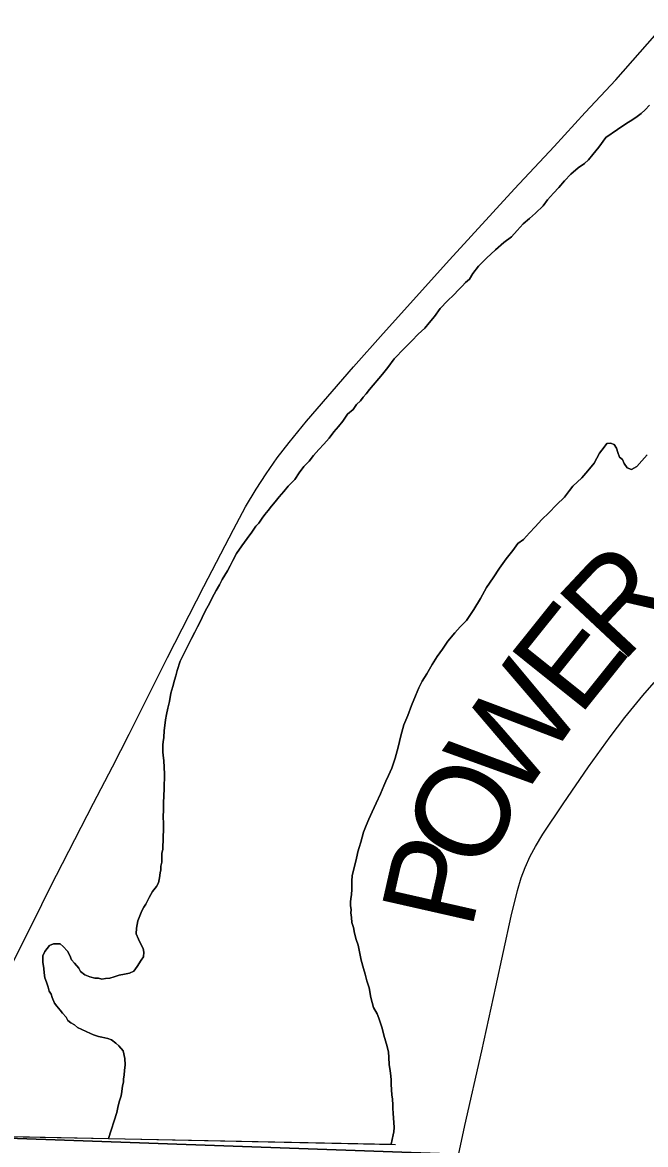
# Model space of a CAD drawing. Extents: x 2.4 to 73.1, y 4.5 to 25.6.
# Drawn here: x 33.9507 to 34.1404, y 20.0736 to 20.4152 of the extents above; entities that cross this region are included whole.
import ezdxf

# ---------------------------------------------------------------- set-up
doc = ezdxf.new("R2010")
doc.units = 0
for name, color, linetype in [('GM_X_County_Road', 7, 'Continuous'), ('GM_X_County_Road_Text', 7, 'Continuous'), ('GM_X_Major_River', 7, 'Continuous'), ('GM_X_Minor_River', 7, 'Continuous'), ('GM_X_State_Route', 7, 'Continuous'), ('SH_Cut_Line', 7, 'Continuous')]:
    doc.layers.add(name, color=color, linetype=linetype)

msp = doc.modelspace()

# ---------------------------------------------------------------- linework, layer by layer
at = {"layer": 'GM_X_County_Road'}
msp.add_lwpolyline([(34.08344, 20.07038), (34.08542, 20.07939), (34.09056, 20.10213), (34.09483, 20.12156), (34.0995, 20.14313), (34.10142, 20.15095), (34.10256, 20.1548), (34.10374, 20.15797), (34.10525, 20.16134), (34.10684, 20.16434), (34.10908, 20.16804), (34.11526, 20.17735), (34.12304, 20.1886), (34.12957, 20.19767), (34.13405, 20.20361), (34.13957, 20.21032), (34.14303, 20.21429)], dxfattribs=at)
at = {"layer": 'GM_X_Major_River'}
for p, q in [((34.06432, 20.07347), (33.88268, 20.07732)), ((33.97691, 20.07544), (34.06299, 20.07369))]:
    msp.add_line(p, q, dxfattribs=at)
for points in [[(34.1416, 20.39007), (34.14022, 20.38859), (34.13904, 20.38749), (34.13787, 20.38658), (34.13651, 20.38567), (34.13437, 20.38441), (34.13184, 20.3826), (34.12833, 20.38024), (34.12615, 20.37727), (34.12436, 20.37505), (34.12297, 20.37338), (34.1218, 20.37228), (34.11985, 20.37101), (34.11769, 20.36899), (34.11572, 20.36696), (34.11394, 20.36493), (34.11237, 20.36327), (34.11059, 20.36124), (34.1092, 20.35938), (34.10684, 20.35718), (34.10507, 20.35552), (34.10312, 20.35388), (34.10134, 20.35184), (34.09957, 20.35), (34.09722, 20.34818), (34.09468, 20.34598), (34.09193, 20.34341), (34.08957, 20.34101), (34.08778, 20.33879)], [(34.08778, 20.33879), (34.08957, 20.34101), (34.09193, 20.34341), (34.09468, 20.34598), (34.09722, 20.34818), (34.09957, 20.35), (34.10134, 20.35184), (34.10312, 20.35388), (34.10507, 20.35552), (34.10684, 20.35718), (34.1092, 20.35938), (34.11059, 20.36124), (34.11237, 20.36327), (34.11394, 20.36493), (34.11572, 20.36696), (34.11769, 20.36899), (34.11985, 20.37101), (34.1218, 20.37228), (34.12297, 20.37338), (34.12436, 20.37505), (34.12615, 20.37727), (34.12833, 20.38024), (34.13184, 20.3826), (34.13437, 20.38441), (34.13651, 20.38567), (34.13787, 20.38658), (34.13904, 20.38749), (34.14022, 20.38859), (34.1416, 20.39007)], [(34.08778, 20.33879), (34.08678, 20.33711), (34.0856, 20.33601), (34.08461, 20.3349), (34.08343, 20.3338), (34.08205, 20.33232), (34.08009, 20.33049), (34.07792, 20.32809), (34.07613, 20.32567), (34.07455, 20.32382), (34.07316, 20.32216), (34.0712, 20.32032), (34.06923, 20.31829), (34.06706, 20.31608), (34.06391, 20.31276), (34.06192, 20.31017), (34.06033, 20.30813), (34.05638, 20.3035), (34.05538, 20.3022), (34.0544, 20.3011), (34.0536, 20.29998), (34.05242, 20.29888), (34.05142, 20.29739), (34.04966, 20.29593), (34.04826, 20.29388), (34.04688, 20.29222), (34.04549, 20.29055), (34.0441, 20.28869), (34.04251, 20.28684), (34.04094, 20.28518), (34.03936, 20.28333), (34.03797, 20.28167), (34.03639, 20.28001), (34.035, 20.27815), (34.0336, 20.27611), (34.03163, 20.27408), (34.03025, 20.27241), (34.02886, 20.27075), (34.02767, 20.26927), (34.02649, 20.26797), (34.02549, 20.26668), (34.0245, 20.26538), (34.0237, 20.26426), (34.0227, 20.26277), (34.02172, 20.26186), (34.02052, 20.25999), (34.01913, 20.25814), (34.01753, 20.25591), (34.01593, 20.25349), (34.01472, 20.25143), (34.01391, 20.24975), (34.0131, 20.24826), (34.01229, 20.24695), (34.01149, 20.24565), (34.01068, 20.24396), (34.00967, 20.24228), (34.00846, 20.24004), (34.00764, 20.23836), (34.00683, 20.23686), (34.00582, 20.23499), (34.005, 20.23312), (34.00399, 20.23125), (34.00317, 20.22956), (34.00216, 20.2277), (34.00134, 20.22601), (33.9987, 20.22077), (33.99785, 20.21795), (33.99741, 20.21625), (33.99699, 20.21493), (33.99655, 20.21304), (33.99591, 20.21097), (33.99545, 20.20852), (33.995, 20.20644), (33.99456, 20.20455), (33.99432, 20.20285), (33.99407, 20.20114), (33.99383, 20.19963), (33.99377, 20.19754), (33.99353, 20.19621), (33.9935, 20.19527), (33.99347, 20.19412), (33.99344, 20.19317), (33.99359, 20.19203), (33.99373, 20.1905), (33.99385, 20.18841), (33.99398, 20.1865), (33.99394, 20.18498), (33.99388, 20.18327), (33.99384, 20.18194), (33.99377, 20.17966), (33.99371, 20.17776), (33.99363, 20.17548), (33.99357, 20.17339), (33.99369, 20.17129), (33.99362, 20.1692), (33.99357, 20.16749), (33.99352, 20.16597), (33.99348, 20.16464), (33.99344, 20.1635), (33.99321, 20.16218), (33.99316, 20.16066)], [(33.99316, 20.16066), (33.99321, 20.16218), (33.99344, 20.1635), (33.99348, 20.16464), (33.99352, 20.16597), (33.99357, 20.16749), (33.99362, 20.1692), (33.99369, 20.17129), (33.99357, 20.17339), (33.99363, 20.17548), (33.99371, 20.17776), (33.99377, 20.17966), (33.99384, 20.18194), (33.99388, 20.18327), (33.99394, 20.18498), (33.99398, 20.1865), (33.99385, 20.18841), (33.99373, 20.1905), (33.99359, 20.19203), (33.99344, 20.19317), (33.99347, 20.19412), (33.9935, 20.19527), (33.99353, 20.19621), (33.99377, 20.19754), (33.99383, 20.19963), (33.99407, 20.20114), (33.99432, 20.20285), (33.99456, 20.20455), (33.995, 20.20644), (33.99545, 20.20852), (33.99591, 20.21097), (33.99655, 20.21304), (33.99699, 20.21493), (33.99741, 20.21625), (33.99785, 20.21795), (33.9987, 20.22077), (34.00134, 20.22601), (34.00216, 20.2277), (34.00317, 20.22956), (34.00399, 20.23125), (34.005, 20.23312), (34.00582, 20.23499), (34.00683, 20.23686), (34.00764, 20.23836), (34.00846, 20.24004), (34.00967, 20.24228), (34.01068, 20.24396), (34.01149, 20.24565), (34.01229, 20.24695), (34.0131, 20.24826), (34.01391, 20.24975), (34.01472, 20.25143), (34.01593, 20.25349), (34.01753, 20.25591), (34.01913, 20.25814), (34.02052, 20.25999), (34.02172, 20.26186), (34.0227, 20.26277), (34.0237, 20.26426), (34.0245, 20.26538), (34.02549, 20.26668), (34.02649, 20.26797), (34.02767, 20.26927), (34.02886, 20.27075), (34.03025, 20.27241), (34.03163, 20.27408), (34.0336, 20.27611), (34.035, 20.27815), (34.03639, 20.28001), (34.03797, 20.28167), (34.03936, 20.28333), (34.04094, 20.28518), (34.04251, 20.28684), (34.0441, 20.28869), (34.04549, 20.29055), (34.04688, 20.29222), (34.04826, 20.29388), (34.04966, 20.29593), (34.05142, 20.29739), (34.05242, 20.29888), (34.0536, 20.29998), (34.0544, 20.3011), (34.05538, 20.3022), (34.05638, 20.3035), (34.06033, 20.30813), (34.06192, 20.31017), (34.06391, 20.31276), (34.06706, 20.31608), (34.06923, 20.31829), (34.0712, 20.32032), (34.07316, 20.32216), (34.07455, 20.32382), (34.07613, 20.32567), (34.07792, 20.32809), (34.08009, 20.33049), (34.08205, 20.33232), (34.08343, 20.3338), (34.08461, 20.3349), (34.0856, 20.33601), (34.08678, 20.33711), (34.08778, 20.33879)], [(34.08396, 20.23125), (34.08593, 20.23309), (34.08813, 20.23644), (34.09014, 20.2398), (34.09196, 20.24316), (34.09396, 20.24614), (34.09596, 20.24911), (34.09795, 20.2519), (34.09994, 20.2545), (34.10153, 20.25654), (34.10328, 20.25781), (34.10506, 20.25984), (34.10683, 20.26169), (34.10881, 20.2639), (34.11097, 20.26592), (34.11333, 20.26832), (34.11569, 20.27071), (34.11728, 20.27275), (34.11827, 20.27405), (34.12102, 20.27662), (34.1228, 20.27866), (34.12478, 20.28106), (34.1264, 20.28405), (34.12779, 20.28591), (34.12859, 20.28702), (34.12974, 20.28718), (34.13087, 20.28676), (34.13159, 20.28559), (34.13193, 20.28425), (34.13246, 20.2829), (34.13339, 20.28211), (34.13392, 20.28095), (34.13483, 20.27959), (34.13615, 20.27916), (34.1377, 20.28006), (34.13928, 20.28172), (34.14086, 20.28357)], [(34.14086, 20.28357), (34.13928, 20.28172), (34.1377, 20.28006), (34.13615, 20.27916), (34.13483, 20.27959), (34.13392, 20.28095), (34.13339, 20.28211), (34.13246, 20.2829), (34.13193, 20.28425), (34.13159, 20.28559), (34.13087, 20.28676), (34.12974, 20.28718), (34.12859, 20.28702), (34.12779, 20.28591), (34.1264, 20.28405), (34.12478, 20.28106), (34.1228, 20.27866), (34.12102, 20.27662), (34.11827, 20.27405), (34.11728, 20.27275), (34.11569, 20.27071), (34.11333, 20.26832), (34.11097, 20.26592), (34.10881, 20.2639), (34.10683, 20.26169), (34.10506, 20.25984), (34.10328, 20.25781), (34.10153, 20.25654), (34.09994, 20.2545), (34.09795, 20.2519), (34.09596, 20.24911), (34.09396, 20.24614), (34.09196, 20.24316), (34.09014, 20.2398), (34.08813, 20.23644), (34.08593, 20.23309), (34.08396, 20.23125)], [(34.06299, 20.07369), (34.06358, 20.07652), (34.06381, 20.07746), (34.06385, 20.07879), (34.06361, 20.08318), (34.06346, 20.08451), (34.0635, 20.08565), (34.06336, 20.08737), (34.06321, 20.08871), (34.06307, 20.09023), (34.06294, 20.09195), (34.06298, 20.09328), (34.06283, 20.09442), (34.06269, 20.09614), (34.06237, 20.09786), (34.06225, 20.10015), (34.06211, 20.10168), (34.06178, 20.1034), (34.06126, 20.10513), (34.06075, 20.10686), (34.06025, 20.10897), (34.05972, 20.11051), (34.0592, 20.11205), (34.05867, 20.1134), (34.05759, 20.11533), (34.05674, 20.1184), (34.05626, 20.12127), (34.05557, 20.12339), (34.05506, 20.1255), (34.05455, 20.12723), (34.05386, 20.12972), (34.05337, 20.13221), (34.05287, 20.13432), (34.05235, 20.13605), (34.05184, 20.13797), (34.05152, 20.13969), (34.051, 20.14123), (34.05085, 20.14276), (34.05071, 20.14409), (34.05074, 20.14504), (34.05059, 20.14638), (34.05062, 20.14733), (34.05066, 20.14847), (34.05088, 20.14961), (34.05094, 20.15132), (34.05097, 20.15246), (34.05102, 20.15379), (34.05107, 20.1555), (34.05216, 20.15983), (34.0526, 20.16172), (34.05282, 20.16267), (34.05325, 20.16398), (34.05368, 20.16568), (34.05411, 20.16719), (34.05454, 20.1687), (34.05537, 20.17076), (34.05619, 20.17264), (34.05721, 20.17488), (34.05844, 20.17751), (34.05967, 20.18032), (34.0607, 20.18276), (34.06132, 20.18426), (34.06214, 20.18594), (34.06316, 20.18819), (34.06421, 20.1912), (34.06508, 20.1946), (34.06595, 20.19799), (34.06682, 20.20139), (34.06805, 20.2042), (34.0691, 20.20721), (34.07034, 20.21021), (34.07137, 20.21265), (34.07239, 20.21471), (34.07379, 20.21694), (34.07541, 20.21974), (34.07701, 20.22216), (34.0786, 20.22439), (34.0802, 20.22681), (34.08238, 20.2294), (34.08396, 20.23125)], [(34.08396, 20.23125), (34.08238, 20.2294), (34.0802, 20.22681), (34.0786, 20.22439), (34.07701, 20.22216), (34.07541, 20.21974), (34.07379, 20.21694), (34.07239, 20.21471), (34.07137, 20.21265), (34.07034, 20.21021), (34.0691, 20.20721), (34.06805, 20.2042), (34.06682, 20.20139), (34.06595, 20.19799), (34.06508, 20.1946), (34.06421, 20.1912), (34.06316, 20.18819), (34.06214, 20.18594), (34.06132, 20.18426), (34.0607, 20.18276), (34.05967, 20.18032), (34.05844, 20.17751), (34.05721, 20.17488), (34.05619, 20.17264), (34.05537, 20.17076), (34.05454, 20.1687), (34.05411, 20.16719), (34.05368, 20.16568), (34.05325, 20.16398), (34.05282, 20.16267), (34.0526, 20.16172), (34.05216, 20.15983), (34.05107, 20.1555), (34.05102, 20.15379), (34.05097, 20.15246), (34.05094, 20.15132), (34.05088, 20.14961), (34.05066, 20.14847), (34.05062, 20.14733), (34.05059, 20.14638), (34.05074, 20.14504), (34.05071, 20.14409), (34.05085, 20.14276), (34.051, 20.14123), (34.05152, 20.13969), (34.05184, 20.13797), (34.05235, 20.13605), (34.05287, 20.13432), (34.05337, 20.13221), (34.05386, 20.12972), (34.05455, 20.12723), (34.05506, 20.1255), (34.05557, 20.12339), (34.05626, 20.12127), (34.05674, 20.1184), (34.05759, 20.11533), (34.05867, 20.1134), (34.0592, 20.11205), (34.05972, 20.11051), (34.06025, 20.10897), (34.06075, 20.10686), (34.06126, 20.10513), (34.06178, 20.1034), (34.06211, 20.10168), (34.06225, 20.10015), (34.06237, 20.09786), (34.06269, 20.09614), (34.06283, 20.09442), (34.06298, 20.09328), (34.06294, 20.09195), (34.06307, 20.09023), (34.06321, 20.08871), (34.06336, 20.08737), (34.0635, 20.08565), (34.06346, 20.08451), (34.06361, 20.08318), (34.06385, 20.07879), (34.06381, 20.07746), (34.06358, 20.07652), (34.06299, 20.07369)], [(33.99316, 20.16066), (33.99312, 20.15952), (33.99289, 20.15838), (33.99286, 20.15724), (33.99264, 20.1563), (33.9924, 20.15478), (33.99216, 20.15327), (33.99155, 20.15215), (33.99036, 20.15067), (33.98935, 20.1488), (33.98833, 20.14674), (33.98773, 20.14581), (33.98712, 20.14469), (33.98671, 20.14375), (33.98589, 20.14169), (33.98566, 20.14055), (33.98543, 20.13942), (33.98538, 20.13771), (33.98609, 20.13616), (33.9868, 20.13462), (33.98752, 20.13326), (33.98767, 20.13211), (33.98763, 20.13078), (33.98683, 20.12967), (33.98563, 20.12781), (33.98463, 20.12632), (33.98328, 20.12579), (33.98175, 20.12546), (33.98021, 20.12513), (33.97867, 20.12461), (33.97733, 20.12428), (33.97599, 20.12413), (33.97485, 20.12398), (33.9739, 20.1242), (33.97276, 20.12424), (33.97125, 20.12467), (33.96975, 20.12529), (33.96845, 20.12629), (33.96791, 20.12725), (33.96662, 20.12882), (33.9657, 20.1298), (33.96517, 20.13115), (33.96446, 20.13251), (33.96317, 20.13388), (33.96224, 20.13467), (33.96129, 20.1347), (33.96015, 20.13474), (33.95899, 20.13421), (33.9576, 20.13235), (33.95698, 20.13104), (33.95695, 20.13009), (33.95692, 20.12914), (33.95724, 20.12723), (33.95739, 20.12589), (33.95753, 20.12437), (33.95806, 20.12302), (33.95858, 20.12148), (33.95892, 20.12033), (33.95946, 20.11936), (33.95981, 20.11839), (33.96052, 20.11666), (33.96125, 20.11568), (33.96217, 20.11451), (33.9629, 20.11354), (33.964, 20.11236), (33.96454, 20.11139), (33.96547, 20.1106), (33.96659, 20.10999), (33.96752, 20.1092), (33.96883, 20.10858), (33.97014, 20.10797), (33.97146, 20.10735), (33.9724, 20.10694), (33.97391, 20.10651), (33.97485, 20.10629), (33.9758, 20.10607), (33.97674, 20.10585), (33.97787, 20.10543), (33.97917, 20.10443), (33.9801, 20.10364), (33.98138, 20.10208), (33.98188, 20.09978), (33.98201, 20.09787), (33.98176, 20.09617), (33.98172, 20.09484), (33.98149, 20.09352), (33.98146, 20.09257), (33.98123, 20.09143), (33.98099, 20.08973), (33.98075, 20.0884), (33.98032, 20.0869), (33.97989, 20.08539), (33.97945, 20.08331), (33.97691, 20.07544)], [(33.97691, 20.07544), (33.97945, 20.08331), (33.97989, 20.08539), (33.98032, 20.0869), (33.98075, 20.0884), (33.98099, 20.08973), (33.98123, 20.09143), (33.98146, 20.09257), (33.98149, 20.09352), (33.98172, 20.09484), (33.98176, 20.09617), (33.98201, 20.09787), (33.98188, 20.09978), (33.98138, 20.10208), (33.9801, 20.10364), (33.97917, 20.10443), (33.97787, 20.10543), (33.97674, 20.10585), (33.9758, 20.10607), (33.97485, 20.10629), (33.97391, 20.10651), (33.9724, 20.10694), (33.97146, 20.10735), (33.97014, 20.10797), (33.96883, 20.10858), (33.96752, 20.1092), (33.96659, 20.10999), (33.96547, 20.1106), (33.96454, 20.11139), (33.964, 20.11236), (33.9629, 20.11354), (33.96217, 20.11451), (33.96125, 20.11568), (33.96052, 20.11666), (33.95981, 20.11839), (33.95946, 20.11936), (33.95892, 20.12033), (33.95858, 20.12148), (33.95806, 20.12302), (33.95753, 20.12437), (33.95739, 20.12589), (33.95724, 20.12723), (33.95692, 20.12914), (33.95695, 20.13009), (33.95698, 20.13104), (33.9576, 20.13235), (33.95899, 20.13421), (33.96015, 20.13474), (33.96129, 20.1347), (33.96224, 20.13467), (33.96317, 20.13388), (33.96446, 20.13251), (33.96517, 20.13115), (33.9657, 20.1298), (33.96662, 20.12882), (33.96791, 20.12725), (33.96845, 20.12629), (33.96975, 20.12529), (33.97125, 20.12467), (33.97276, 20.12424), (33.9739, 20.1242), (33.97485, 20.12398), (33.97599, 20.12413), (33.97733, 20.12428), (33.97867, 20.12461), (33.98021, 20.12513), (33.98175, 20.12546), (33.98328, 20.12579), (33.98463, 20.12632), (33.98563, 20.12781), (33.98683, 20.12967), (33.98763, 20.13078), (33.98767, 20.13211), (33.98752, 20.13326), (33.9868, 20.13462), (33.98609, 20.13616), (33.98538, 20.13771), (33.98543, 20.13942), (33.98566, 20.14055), (33.98589, 20.14169), (33.98671, 20.14375), (33.98712, 20.14469), (33.98773, 20.14581), (33.98833, 20.14674), (33.98935, 20.1488), (33.99036, 20.15067), (33.99155, 20.15215), (33.99216, 20.15327), (33.9924, 20.15478), (33.99264, 20.1563), (33.99286, 20.15724), (33.99289, 20.15838), (33.99312, 20.15952), (33.99316, 20.16066)]]:
    msp.add_lwpolyline(points, dxfattribs=at)
at = {"layer": 'GM_X_Minor_River'}
msp.add_lwpolyline([(33.90407, 20.07689), (33.97691, 20.07544)], dxfattribs=at)
at = {"layer": 'GM_X_State_Route'}
msp.add_lwpolyline([(33.94697, 20.12735), (33.95407, 20.14153), (33.95918, 20.15183), (33.97237, 20.17756), (33.9781, 20.1886), (33.98322, 20.19854), (33.98655, 20.20521), (33.99484, 20.22192), (34.00594, 20.24348), (34.01496, 20.26087), (34.01866, 20.26772), (34.02185, 20.27308), (34.02489, 20.2778), (34.02829, 20.28265), (34.03187, 20.28737), (34.03722, 20.29385), (34.05145, 20.31033), (34.06055, 20.32055), (34.08075, 20.34294), (34.10045, 20.36453), (34.11254, 20.37748), (34.12201, 20.38777), (34.13131, 20.39779), (34.14841, 20.4171)], dxfattribs=at)
at = {"layer": 'SH_Cut_Line'}
for points in [[(34.08332, 20.07065), (33.92065, 20.07639)], [(33.92065, 20.07639), (34.08332, 20.07065)]]:
    msp.add_lwpolyline(points, dxfattribs=at)

# ---------------------------------------------------------------- texts
at = {"layer": 'GM_X_County_Road_Text'}
for s, rotation, p in [('R', 46.9046, (34.13305, 20.21972)), ('E', 51.3067, (34.12014, 20.20357)), ('W', 54.9439, (34.10152, 20.17701)), ('O', 63.7363, (34.09104, 20.15558)), ('P', 77.2344, (34.0874, 20.13855))]:
    msp.add_text(s, height=0.02841, rotation=rotation, dxfattribs=at).set_placement(p)

doc.saveas('drawing.dxf')
